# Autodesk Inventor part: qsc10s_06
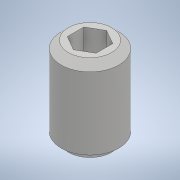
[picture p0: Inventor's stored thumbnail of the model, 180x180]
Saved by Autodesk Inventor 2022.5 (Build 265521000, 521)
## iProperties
Part Number: qsc10s_06
Material: 一般
Document SubType Name: Modeling
Designer: ImaoCorp
Density: 1 g/cm^3
Appearance: 既定
Author: ImaoCorp
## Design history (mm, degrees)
feature "qsc10s_06"
node "ソリッド1"
